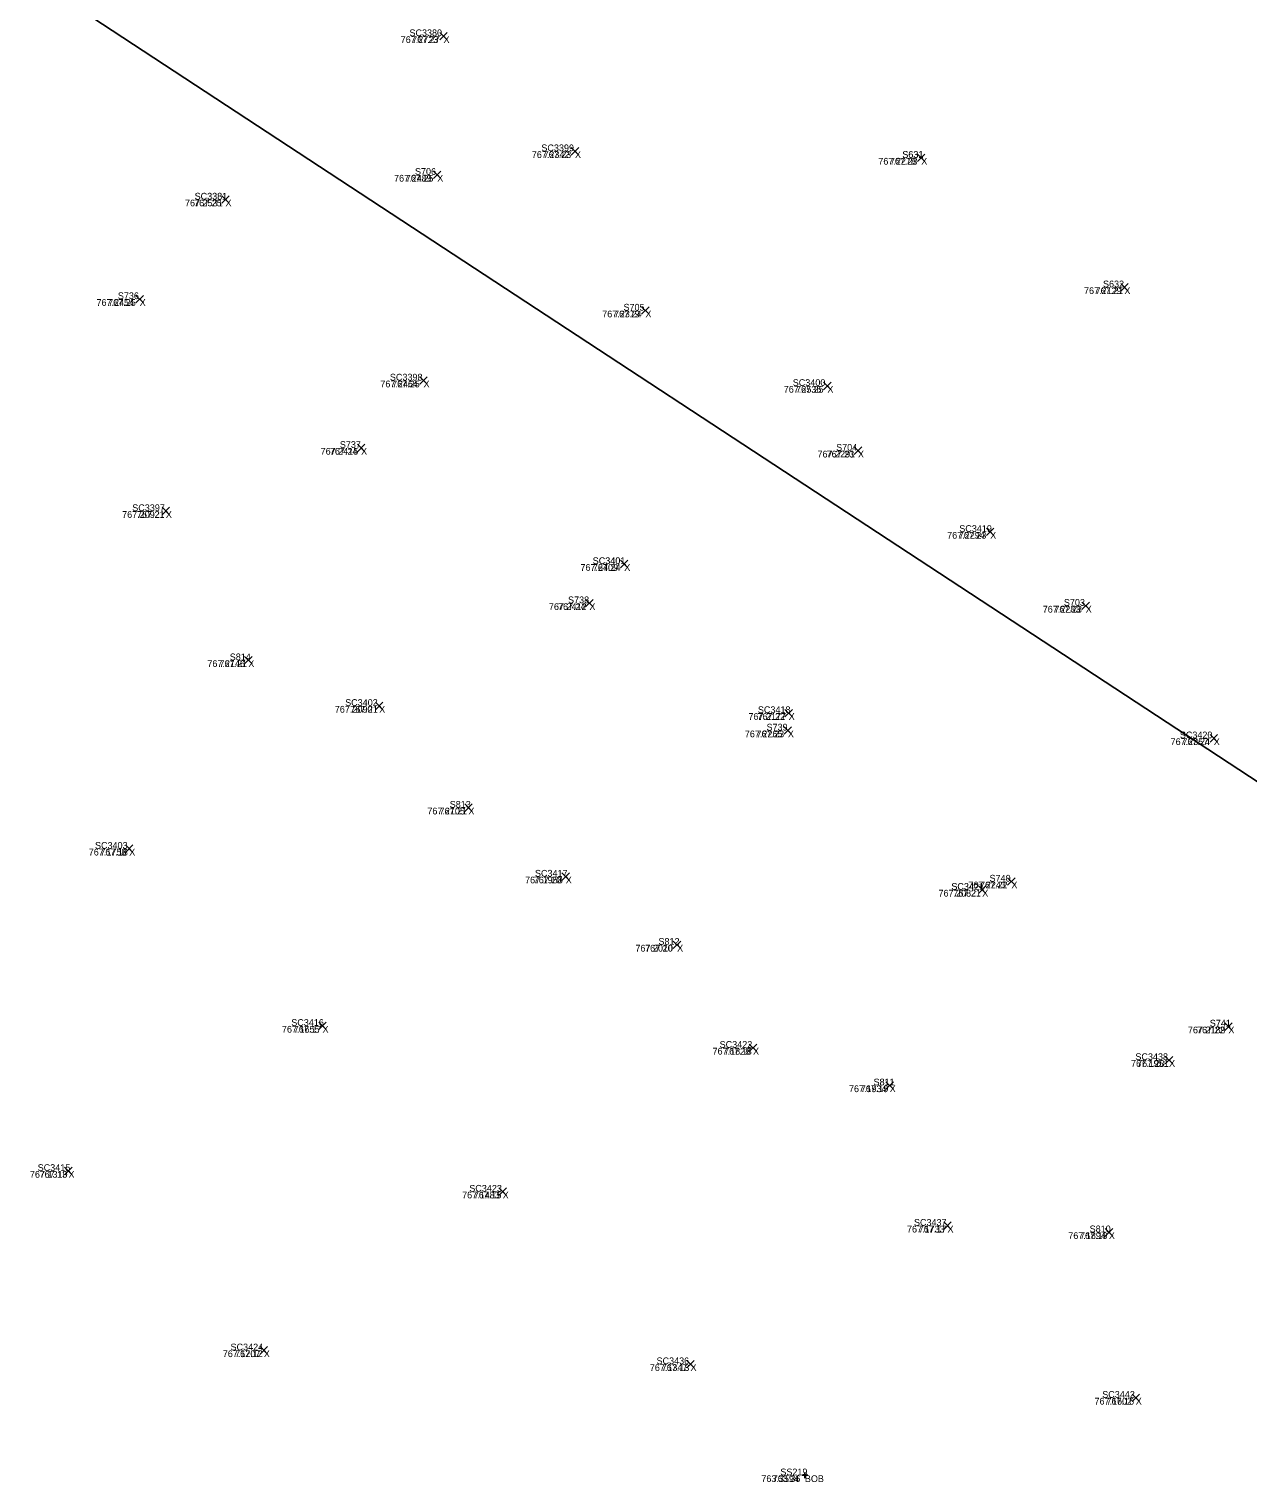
# Model space of a CAD drawing. Extents: x 1845019 to 1877956, y 680444 to 701081.
# Drawn here: x 1857746.31 to 1857757.15, y 694212.26 to 694225.19 of the extents above; entities that cross this region are included whole.
import ezdxf

# ---------------------------------------------------------------- set-up
doc = ezdxf.new("R2010")
doc.units = 0
for name, color, linetype in [('BR_X_SV_Bottom_of_Beam_Text', 7, 'Continuous'), ('SV_X_CL_Survey_20', 7, 'Continuous'), ('SV_X_Random_Point', 7, 'Continuous'), ('SV_X_Text_Comment', 7, 'Continuous'), ('SV_X_Text_Elevation', 7, 'Continuous'), ('SV_X_Text_Name', 7, 'Continuous')]:
    doc.layers.add(name, color=color, linetype=linetype)

msp = doc.modelspace()

# ---------------------------------------------------------------- linework, layer by layer
at = {"layer": 'BR_X_SV_Bottom_of_Beam_Text'}
for p, q in [((1857753.211, 694212.352), (1857753.211, 694212.302)), ((1857753.211, 694212.352), (1857753.211, 694212.302)), ((1857753.186, 694212.327), (1857753.236, 694212.327)), ((1857753.186, 694212.327), (1857753.236, 694212.327)), ((1857753.211, 694212.327), (1857753.211, 694212.327)), ((1857753.211, 694212.327), (1857753.211, 694212.327))]:
    msp.add_line(p, q, dxfattribs=at)
at = {"layer": 'SV_X_CL_Survey_20'}
msp.add_line((1856038.267, 695346.314), (1858797.327, 693536.085), dxfattribs=at)
at = {"layer": 'SV_X_Random_Point'}
for p, q in [((1857749.965, 694225.09), (1857750.031, 694225.156)), ((1857749.965, 694225.156), (1857750.031, 694225.09)), ((1857749.965, 694225.09), (1857750.031, 694225.156)), ((1857749.965, 694225.156), (1857750.031, 694225.09)), ((1857751.134, 694224.066), (1857751.201, 694224.133)), ((1857751.134, 694224.133), (1857751.201, 694224.066)), ((1857751.134, 694224.066), (1857751.201, 694224.133)), ((1857751.134, 694224.133), (1857751.201, 694224.066)), ((1857754.212, 694224.008), (1857754.279, 694224.075)), ((1857754.212, 694224.075), (1857754.279, 694224.008)), ((1857754.212, 694224.008), (1857754.279, 694224.075)), ((1857754.212, 694224.075), (1857754.279, 694224.008)), ((1857749.908, 694223.857), (1857749.975, 694223.924)), ((1857749.908, 694223.924), (1857749.975, 694223.857)), ((1857749.908, 694223.857), (1857749.975, 694223.924)), ((1857749.908, 694223.924), (1857749.975, 694223.857)), ((1857748.026, 694223.637), (1857748.093, 694223.703)), ((1857748.026, 694223.703), (1857748.093, 694223.637)), ((1857748.026, 694223.637), (1857748.093, 694223.703)), ((1857748.026, 694223.703), (1857748.093, 694223.637)), ((1857747.262, 694222.752), (1857747.329, 694222.818)), ((1857747.262, 694222.818), (1857747.329, 694222.752)), ((1857747.262, 694222.752), (1857747.329, 694222.818)), ((1857747.262, 694222.818), (1857747.329, 694222.752)), ((1857756.019, 694222.857), (1857756.086, 694222.923)), ((1857756.019, 694222.923), (1857756.086, 694222.857)), ((1857756.019, 694222.857), (1857756.086, 694222.923)), ((1857756.019, 694222.923), (1857756.086, 694222.857)), ((1857751.759, 694222.65), (1857751.826, 694222.716)), ((1857751.759, 694222.716), (1857751.826, 694222.65)), ((1857751.759, 694222.65), (1857751.826, 694222.716)), ((1857751.759, 694222.716), (1857751.826, 694222.65)), ((1857749.787, 694222.028), (1857749.853, 694222.094)), ((1857749.787, 694222.094), (1857749.853, 694222.028)), ((1857749.787, 694222.028), (1857749.853, 694222.094)), ((1857749.787, 694222.094), (1857749.853, 694222.028)), ((1857753.378, 694221.979), (1857753.444, 694222.046)), ((1857753.378, 694222.046), (1857753.444, 694221.979)), ((1857753.378, 694221.979), (1857753.444, 694222.046)), ((1857753.378, 694222.046), (1857753.444, 694221.979)), ((1857749.232, 694221.428), (1857749.299, 694221.495)), ((1857749.232, 694221.495), (1857749.299, 694221.428)), ((1857749.232, 694221.428), (1857749.299, 694221.495)), ((1857749.232, 694221.495), (1857749.299, 694221.428)), ((1857753.65, 694221.404), (1857753.716, 694221.471)), ((1857753.65, 694221.471), (1857753.716, 694221.404)), ((1857753.65, 694221.404), (1857753.716, 694221.471)), ((1857753.65, 694221.471), (1857753.716, 694221.404)), ((1857747.495, 694220.867), (1857747.562, 694220.934)), ((1857747.495, 694220.934), (1857747.562, 694220.867)), ((1857747.495, 694220.867), (1857747.562, 694220.934)), ((1857747.495, 694220.934), (1857747.562, 694220.867)), ((1857754.825, 694220.682), (1857754.892, 694220.748)), ((1857754.825, 694220.748), (1857754.892, 694220.682)), ((1857754.825, 694220.682), (1857754.892, 694220.748)), ((1857754.825, 694220.748), (1857754.892, 694220.682)), ((1857751.571, 694220.396), (1857751.638, 694220.463)), ((1857751.571, 694220.463), (1857751.638, 694220.396)), ((1857751.571, 694220.396), (1857751.638, 694220.463)), ((1857751.571, 694220.463), (1857751.638, 694220.396)), ((1857751.261, 694220.048), (1857751.328, 694220.114)), ((1857751.261, 694220.114), (1857751.328, 694220.048)), ((1857751.261, 694220.048), (1857751.328, 694220.114)), ((1857751.261, 694220.114), (1857751.328, 694220.048)), ((1857755.675, 694220.024), (1857755.741, 694220.091)), ((1857755.675, 694220.091), (1857755.741, 694220.024)), ((1857755.675, 694220.024), (1857755.741, 694220.091)), ((1857755.675, 694220.091), (1857755.741, 694220.024)), ((1857748.229, 694219.541), (1857748.295, 694219.607)), ((1857748.229, 694219.607), (1857748.295, 694219.541)), ((1857748.229, 694219.541), (1857748.295, 694219.607)), ((1857748.229, 694219.607), (1857748.295, 694219.541)), ((1857749.392, 694219.134), (1857749.459, 694219.201)), ((1857749.392, 694219.201), (1857749.459, 694219.134)), ((1857749.392, 694219.134), (1857749.459, 694219.201)), ((1857749.392, 694219.201), (1857749.459, 694219.134)), ((1857753.034, 694219.07), (1857753.101, 694219.137)), ((1857753.034, 694219.137), (1857753.101, 694219.07)), ((1857753.034, 694219.07), (1857753.101, 694219.137)), ((1857753.034, 694219.137), (1857753.101, 694219.07)), ((1857753.026, 694218.916), (1857753.093, 694218.982)), ((1857753.026, 694218.982), (1857753.093, 694218.916)), ((1857753.026, 694218.916), (1857753.093, 694218.982)), ((1857753.026, 694218.982), (1857753.093, 694218.916)), ((1857756.814, 694218.847), (1857756.88, 694218.913)), ((1857756.814, 694218.913), (1857756.88, 694218.847)), ((1857756.814, 694218.847), (1857756.88, 694218.913)), ((1857756.814, 694218.913), (1857756.88, 694218.847)), ((1857750.186, 694218.23), (1857750.252, 694218.297)), ((1857750.186, 694218.297), (1857750.252, 694218.23)), ((1857750.186, 694218.23), (1857750.252, 694218.297)), ((1857750.186, 694218.297), (1857750.252, 694218.23)), ((1857747.169, 694217.865), (1857747.236, 694217.932)), ((1857747.169, 694217.932), (1857747.236, 694217.865)), ((1857747.169, 694217.865), (1857747.236, 694217.932)), ((1857747.169, 694217.932), (1857747.236, 694217.865)), ((1857751.051, 694217.617), (1857751.118, 694217.684)), ((1857751.051, 694217.684), (1857751.118, 694217.617)), ((1857751.051, 694217.617), (1857751.118, 694217.684)), ((1857751.051, 694217.684), (1857751.118, 694217.617)), ((1857755.014, 694217.573), (1857755.08, 694217.64)), ((1857755.014, 694217.64), (1857755.08, 694217.573)), ((1857755.014, 694217.573), (1857755.08, 694217.64)), ((1857755.014, 694217.64), (1857755.08, 694217.573)), ((1857754.754, 694217.5), (1857754.821, 694217.567)), ((1857754.754, 694217.567), (1857754.821, 694217.5)), ((1857754.754, 694217.5), (1857754.821, 694217.567)), ((1857754.754, 694217.567), (1857754.821, 694217.5)), ((1857752.041, 694217.011), (1857752.108, 694217.077)), ((1857752.041, 694217.077), (1857752.108, 694217.011)), ((1857752.041, 694217.011), (1857752.108, 694217.077)), ((1857752.041, 694217.077), (1857752.108, 694217.011)), ((1857748.889, 694216.29), (1857748.955, 694216.356)), ((1857748.889, 694216.356), (1857748.955, 694216.29)), ((1857748.889, 694216.29), (1857748.955, 694216.356)), ((1857748.889, 694216.356), (1857748.955, 694216.29)), ((1857756.944, 694216.283), (1857757.011, 694216.35)), ((1857756.944, 694216.35), (1857757.011, 694216.283)), ((1857756.944, 694216.283), (1857757.011, 694216.35)), ((1857756.944, 694216.35), (1857757.011, 694216.283)), ((1857752.716, 694216.094), (1857752.783, 694216.161)), ((1857752.716, 694216.161), (1857752.783, 694216.094)), ((1857752.716, 694216.094), (1857752.783, 694216.161)), ((1857752.716, 694216.161), (1857752.783, 694216.094)), ((1857756.416, 694215.985), (1857756.483, 694216.052)), ((1857756.416, 694216.052), (1857756.483, 694215.985)), ((1857756.416, 694215.985), (1857756.483, 694216.052)), ((1857756.416, 694216.052), (1857756.483, 694215.985)), ((1857753.931, 694215.76), (1857753.998, 694215.827)), ((1857753.931, 694215.827), (1857753.998, 694215.76)), ((1857753.931, 694215.76), (1857753.998, 694215.827)), ((1857753.931, 694215.827), (1857753.998, 694215.76)), ((1857746.629, 694214.999), (1857746.696, 694215.066)), ((1857746.629, 694215.066), (1857746.696, 694214.999)), ((1857746.629, 694214.999), (1857746.696, 694215.066)), ((1857746.629, 694215.066), (1857746.696, 694214.999)), ((1857750.49, 694214.816), (1857750.557, 694214.882)), ((1857750.49, 694214.882), (1857750.557, 694214.816)), ((1857750.49, 694214.816), (1857750.557, 694214.882)), ((1857750.49, 694214.882), (1857750.557, 694214.816)), ((1857754.446, 694214.513), (1857754.512, 694214.58)), ((1857754.446, 694214.58), (1857754.512, 694214.513)), ((1857754.446, 694214.513), (1857754.512, 694214.58)), ((1857754.446, 694214.58), (1857754.512, 694214.513)), ((1857755.881, 694214.454), (1857755.948, 694214.521)), ((1857755.881, 694214.521), (1857755.948, 694214.454)), ((1857755.881, 694214.454), (1857755.948, 694214.521)), ((1857755.881, 694214.521), (1857755.948, 694214.454)), ((1857748.367, 694213.405), (1857748.434, 694213.471)), ((1857748.367, 694213.471), (1857748.434, 694213.405)), ((1857748.367, 694213.405), (1857748.434, 694213.471)), ((1857748.367, 694213.471), (1857748.434, 694213.405)), ((1857752.161, 694213.282), (1857752.228, 694213.349)), ((1857752.161, 694213.349), (1857752.228, 694213.282)), ((1857752.161, 694213.282), (1857752.228, 694213.349)), ((1857752.161, 694213.349), (1857752.228, 694213.282)), ((1857756.12, 694212.982), (1857756.186, 694213.049)), ((1857756.12, 694213.049), (1857756.186, 694212.982)), ((1857756.12, 694212.982), (1857756.186, 694213.049)), ((1857756.12, 694213.049), (1857756.186, 694212.982))]:
    msp.add_line(p, q, dxfattribs=at)

# ---------------------------------------------------------------- texts
at = {"layer": 'BR_X_SV_Bottom_of_Beam_Text'}
for s, p in [('SS219', (1857752.993, 694212.327)), ('SS219', (1857752.993, 694212.327)), ('763.3594', (1857752.824, 694212.267)), ('763.36', (1857752.925, 694212.267)), ('BOB', (1857753.211, 694212.267))]:
    msp.add_text(s, height=0.06, dxfattribs=at).set_placement(p)
at = {"layer": 'SV_X_Text_Comment'}
for p in [(1857749.998, 694225.063), (1857751.167, 694224.04), (1857754.246, 694223.981), (1857749.942, 694223.83), (1857748.059, 694223.61), (1857756.052, 694222.83), (1857747.296, 694222.725), (1857751.793, 694222.623), (1857749.82, 694222.001), (1857753.411, 694221.953), (1857749.265, 694221.402), (1857753.683, 694221.377), (1857747.529, 694220.84), (1857754.859, 694220.655), (1857751.605, 694220.369), (1857751.295, 694220.021), (1857755.708, 694219.998), (1857748.262, 694219.514), (1857749.426, 694219.108), (1857753.067, 694219.044), (1857753.06, 694218.889), (1857756.847, 694218.82), (1857750.219, 694218.203), (1857747.203, 694217.838), (1857751.085, 694217.59), (1857754.788, 694217.473), (1857755.047, 694217.546), (1857752.075, 694216.984), (1857748.922, 694216.263), (1857756.977, 694216.257), (1857752.75, 694216.068), (1857756.449, 694215.959), (1857753.965, 694215.734), (1857746.663, 694214.973), (1857750.524, 694214.789), (1857754.479, 694214.486), (1857755.914, 694214.428), (1857748.4, 694213.378), (1857752.194, 694213.255), (1857756.153, 694212.956)]:
    msp.add_text('X', height=0.06, dxfattribs=at).set_placement(p)
at = {"layer": 'SV_X_Text_Elevation'}
for s, p in [('767.2723', (1857749.617, 694225.063)), ('767.27', (1857749.719, 694225.063)), ('767.2342', (1857750.783, 694224.04)), ('767.23', (1857750.888, 694224.04)), ('767.2278', (1857753.864, 694223.981)), ('767.23', (1857753.967, 694223.981)), ('767.2489', (1857749.558, 694223.83)), ('767.25', (1857749.662, 694223.83)), ('767.2531', (1857747.699, 694223.61)), ('767.25', (1857747.78, 694223.61)), ('767.2129', (1857755.693, 694222.83)), ('767.21', (1857755.796, 694222.83)), ('767.2454', (1857746.912, 694222.725)), ('767.25', (1857747.016, 694222.725)), ('767.2379', (1857751.409, 694222.623)), ('767.24', (1857751.514, 694222.623)), ('767.2464', (1857749.436, 694222.001)), ('767.25', (1857749.541, 694222.001)), ('767.2536', (1857753.023, 694221.953)), ('767.25', (1857753.132, 694221.953)), ('767.2415', (1857748.905, 694221.402)), ('767.24', (1857748.987, 694221.402)), ('767.2291', (1857753.323, 694221.377)), ('767.23', (1857753.404, 694221.377)), ('767.2092', (1857747.14, 694220.84)), ('767.21', (1857747.272, 694220.84)), ('767.2294', (1857754.476, 694220.655)), ('767.23', (1857754.579, 694220.655)), ('767.2409', (1857751.215, 694220.369)), ('767.24', (1857751.326, 694220.369)), ('767.2412', (1857750.935, 694220.021)), ('767.24', (1857751.016, 694220.021)), ('767.2283', (1857755.326, 694219.998)), ('767.23', (1857755.429, 694219.998)), ('767.2146', (1857747.898, 694219.514)), ('767.21', (1857748.005, 694219.514)), ('767.2090', (1857749.031, 694219.108)), ('767.21', (1857749.169, 694219.108)), ('767.2177', (1857752.709, 694219.044)), ('767.22', (1857752.789, 694219.044)), ('767.2265', (1857752.677, 694218.889)), ('767.23', (1857752.781, 694218.889)), ('767.2357', (1857756.463, 694218.82)), ('767.24', (1857756.568, 694218.82)), ('767.2105', (1857749.854, 694218.203)), ('767.21', (1857749.962, 694218.203)), ('767.1758', (1857746.843, 694217.838)), ('767.18', (1857746.946, 694217.838)), ('767.1958', (1857750.723, 694217.59)), ('767.20', (1857750.8, 694217.59)), ('767.2082', (1857754.399, 694217.473)), ('767.21', (1857754.531, 694217.473)), ('767.2243', (1857754.664, 694217.546)), ('767.22', (1857754.768, 694217.546)), ('767.2010', (1857751.704, 694216.984)), ('767.20', (1857751.79, 694216.984)), ('767.1655', (1857748.561, 694216.263)), ('767.17', (1857748.666, 694216.263)), ('767.2189', (1857756.617, 694216.257)), ('767.22', (1857756.698, 694216.257)), ('767.1828', (1857752.39, 694216.068)), ('767.18', (1857752.493, 694216.068)), ('767.1951', (1857756.111, 694215.959)), ('767.20', (1857756.165, 694215.959)), ('767.1934', (1857753.603, 694215.734)), ('767.19', (1857753.708, 694215.734)), ('767.1310', (1857746.32, 694214.973)), ('767.13', (1857746.406, 694214.973)), ('767.1483', (1857750.163, 694214.789)), ('767.15', (1857750.267, 694214.789)), ('767.1733', (1857754.119, 694214.486)), ('767.17', (1857754.223, 694214.486)), ('767.1894', (1857755.553, 694214.428)), ('767.19', (1857755.657, 694214.428)), ('767.1207', (1857748.035, 694213.378)), ('767.12', (1857748.144, 694213.378)), ('767.1347', (1857751.832, 694213.255)), ('767.13', (1857751.938, 694213.255)), ('767.1602', (1857755.786, 694212.956)), ('767.16', (1857755.893, 694212.956))]:
    msp.add_text(s, height=0.06, dxfattribs=at).set_placement(p)
at = {"layer": 'SV_X_Text_Name'}
for s, p in [('SC3380', (1857749.695, 694225.123)), ('SC3380', (1857749.695, 694225.123)), ('SC3399', (1857750.868, 694224.1)), ('SC3399', (1857750.868, 694224.1)), ('S631', (1857754.077, 694224.041)), ('S631', (1857754.078, 694224.041)), ('S706', (1857749.744, 694223.89)), ('S706', (1857749.744, 694223.89)), ('SC3381', (1857747.784, 694223.67)), ('SC3381', (1857747.785, 694223.67)), ('S632', (1857755.862, 694222.89)), ('S632', (1857755.862, 694222.89)), ('S736', (1857747.102, 694222.785)), ('S736', (1857747.102, 694222.785)), ('S705', (1857751.598, 694222.683)), ('S705', (1857751.598, 694222.683)), ('SC3398', (1857749.521, 694222.061)), ('SC3398', (1857749.521, 694222.061)), ('SC3400', (1857753.103, 694222.013)), ('SC3400', (1857753.103, 694222.013)), ('S737', (1857749.076, 694221.462)), ('S737', (1857749.076, 694221.462)), ('S704', (1857753.489, 694221.437)), ('S704', (1857753.489, 694221.437)), ('SC3397', (1857747.23, 694220.9)), ('SC3397', (1857747.23, 694220.9)), ('SC3419', (1857754.584, 694220.715)), ('SC3419', (1857754.584, 694220.715)), ('SC3401', (1857751.324, 694220.429)), ('SC3401', (1857751.325, 694220.429)), ('S738', (1857751.105, 694220.081)), ('S738', (1857751.105, 694220.081)), ('S703', (1857755.514, 694220.058)), ('S703', (1857755.514, 694220.058)), ('S814', (1857748.097, 694219.574)), ('S814', (1857748.097, 694219.574)), ('SC3402', (1857749.123, 694219.168)), ('SC3402', (1857749.123, 694219.168)), ('SC3418', (1857752.793, 694219.104)), ('SC3418', (1857752.793, 694219.104)), ('S739', (1857752.87, 694218.949)), ('S739', (1857752.87, 694218.949)), ('SC3420', (1857756.545, 694218.88)), ('SC3420', (1857756.545, 694218.88)), ('S813', (1857750.053, 694218.263)), ('S813', (1857750.053, 694218.263)), ('SC3403', (1857746.899, 694217.898)), ('SC3403', (1857746.899, 694217.898)), ('SC3417', (1857750.811, 694217.65)), ('SC3417', (1857750.811, 694217.65)), ('S740', (1857754.853, 694217.606)), ('S740', (1857754.853, 694217.606)), ('SC3421', (1857754.513, 694217.533)), ('SC3421', (1857754.514, 694217.533)), ('S812', (1857751.909, 694217.044)), ('S812', (1857751.909, 694217.044)), ('SC3416', (1857748.644, 694216.323)), ('SC3416', (1857748.644, 694216.323)), ('S741', (1857756.811, 694216.317)), ('S741', (1857756.812, 694216.317)), ('SC3422', (1857752.453, 694216.128)), ('SC3422', (1857752.453, 694216.128)), ('SC3438', (1857756.15, 694216.019)), ('SC3438', (1857756.15, 694216.019)), ('S811', (1857753.821, 694215.794)), ('S811', (1857753.822, 694215.794)), ('SC3415', (1857746.389, 694215.033)), ('SC3415', (1857746.389, 694215.033)), ('SC3423', (1857750.227, 694214.849)), ('SC3423', (1857750.227, 694214.849)), ('SC3437', (1857754.181, 694214.546)), ('SC3437', (1857754.181, 694214.546)), ('S810', (1857755.743, 694214.488)), ('S810', (1857755.743, 694214.488)), ('SC3424', (1857748.104, 694213.438)), ('SC3424', (1857748.104, 694213.438)), ('SC3436', (1857751.892, 694213.315)), ('SC3436', (1857751.892, 694213.315)), ('SC3442', (1857755.855, 694213.016)), ('SC3442', (1857755.855, 694213.016))]:
    msp.add_text(s, height=0.06, dxfattribs=at).set_placement(p)

doc.saveas('drawing.dxf')
